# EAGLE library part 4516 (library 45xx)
Binary up down COUNTER
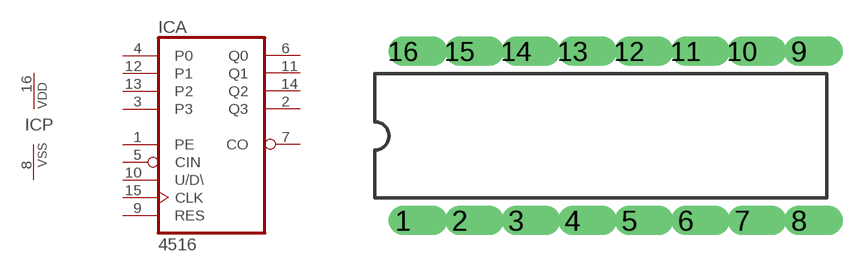
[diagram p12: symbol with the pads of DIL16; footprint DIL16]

Designator prefix IC; gates A=4516 P=PWRN

## 4516N  [DIL16]
1  A:PE  in
2  A:Q3  out
3  A:P3  in
4  A:P0  in
5  A:CIN  in
6  A:Q0  out
7  A:CO  out
8  P:VSS  pwr
9  A:RES  in
10  A:U/D\  in
11  A:Q1  out
12  A:P1  in
13  A:P2  in
14  A:Q2  out
15  A:CLK  in
16  P:VDD  pwr

## Footprint DIL16 (pad centres in mm)
Dual In Line
drill 0.813 offset: 1 -8.89,-3.81; 2 -6.35,-3.81; 3 -3.81,-3.81; 4 -1.27,-3.81; 5 1.27,-3.81; 6 3.81,-3.81; 7 6.35,-3.81; 8 8.89,-3.81; 9 8.89,3.81; 10 6.35,3.81; 11 3.81,3.81; 12 1.27,3.81; 13 -1.27,3.81; 14 -3.81,3.81; 15 -6.35,3.81; 16 -8.89,3.81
